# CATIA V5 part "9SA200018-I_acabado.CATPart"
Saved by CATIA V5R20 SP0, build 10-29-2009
Part number: 9SA200018-I_acabado
Revision: ANY
Definition: UNKNOWN
Nomenclature: 9SA200018-I_acabado
Source: Unknown
Bounding box of the stored display mesh (mm): x -5.752 to 5.752, y -16 to 3, z -5.9 to 5.9
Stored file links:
  C:\Users\Utente\Desktop\IO LAVORO\3D X SITO CF\CUMSA\3D files SA\SA 200018\9SA200018-I_acabado.CATPart
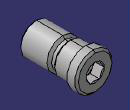
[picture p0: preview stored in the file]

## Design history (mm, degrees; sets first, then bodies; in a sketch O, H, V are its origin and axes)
Body1 "Cortar-Extruir1" (main body)
  Solid1: solid without history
